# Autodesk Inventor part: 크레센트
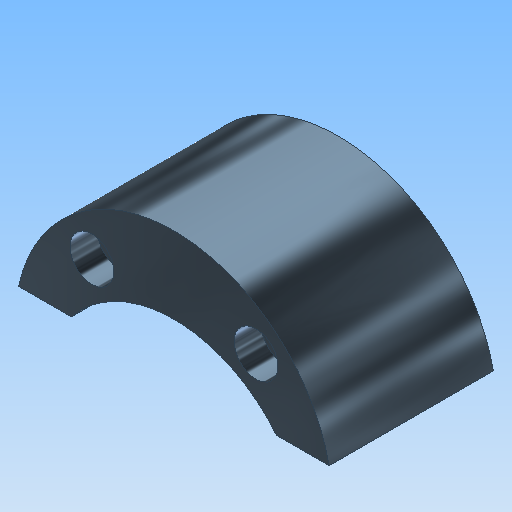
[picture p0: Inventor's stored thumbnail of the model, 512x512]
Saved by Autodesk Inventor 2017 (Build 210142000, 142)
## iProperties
Created: 2023-11
Part Number: 크레센트
Material: 강철, 합금
Document SubType Name: Modeling
Designer: mdu-01
Density: 1 g/cm^3
Appearance: 반광택(1)
Author: mdu-01
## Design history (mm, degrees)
sketch "스케치1"
  geometry: L1 (-28.373, 15)-(-18.735, 15); L2 (18.735, 15)-(28.373, 15); A1 r 24 centre (0, 0) between (-18.735, 15) and (18.735, 15); A2 r 29 centre (0, 9) between (-28.373, 15) and (28.373, 15); 1 further point
  constraints: 4 end point, 4 point on circle, 2 centre point, 2 horizontal, 1 coincident, 1 collinear, 1 vertical alignment
  dimensions: "d0" = 9 distance of A2.centre A1.centre; "d2" = 48 diameter of A1; "d3" = 58 diameter of A2; "d5" = 6 distance from line of L2 A2.centre
extrude "돌출1" new body sketch "스케치1" distance "d6" = 30; taper "d7" = 0 deg
sketch "스케치2"
  geometry: L1 (-15, 26)-(15, 26); L2 (18.735, 15)-(28.373, 15) reference; 2 further points
  constraints: 2 end point, 1 horizontal, 1 midpoint, 1 vertical alignment
  dimensions: "d8" = 11 distance between parallel lines of L1 L2; "d9" = 30 distance of L1.start L1.end
hole "구멍1" sketch "스케치2" at (15, 26), (-15, 26) diameter "d10" = 4.5; stored, may be unused: countersink angle "d14" = 90 deg, drill point angle "d16" = 118 deg; dims "d11" = 6, "d12" = 8, "d13" = 5, "d15" = 8
node "솔리드1"
other parameters: "d4" = 6
